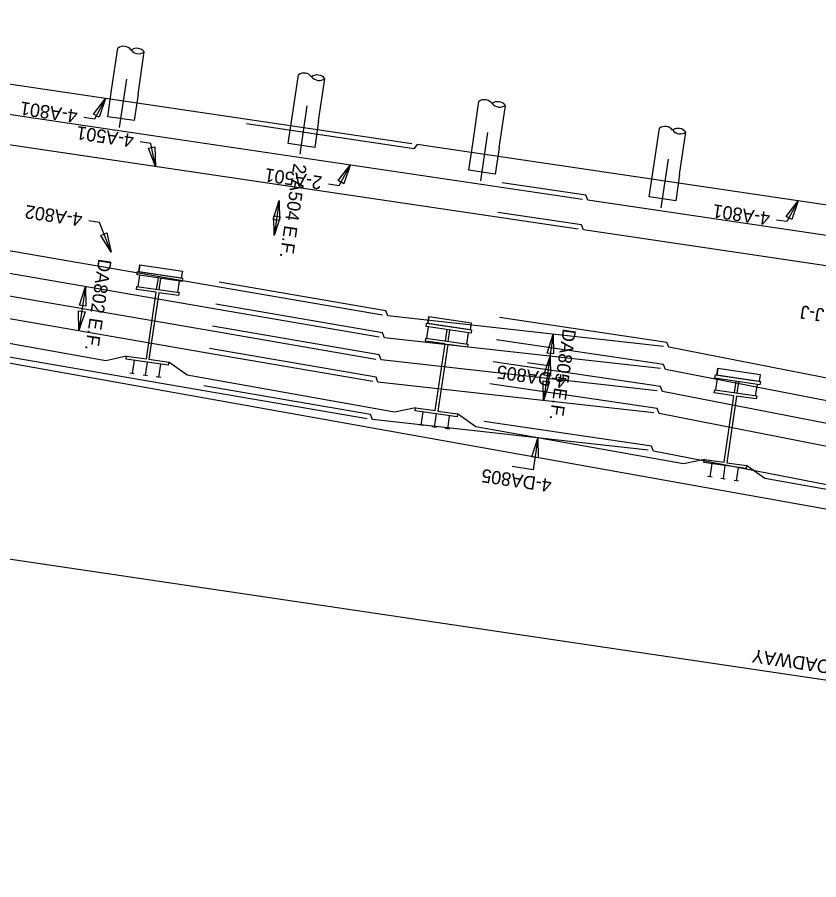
# Model space of a CAD drawing. Extents: x 1467956 to 1469946, y 573734 to 574139.
# Drawn here: x 1468989.52 to 1469019.53, y 574056.5 to 574088.79 of the extents above; entities that cross this region are included whole.
import ezdxf

# ---------------------------------------------------------------- set-up
doc = ezdxf.new("R2010")
doc.units = 0
for name, color, linetype in [('BR_P_Beam_Object', 7, 'Continuous'), ('BR_P_Beam_Stl_Det_Hidden', 7, 'Continuous'), ('BR_P_Brg_Pad_Object', 7, 'Continuous'), ('BR_P_Dia_Reinforcing', 7, 'Continuous'), ('BR_P_Gen_Text', 7, 'Continuous'), ('BR_P_Slab_Object', 7, 'Continuous'), ('BR_P_Sub_Deep_Centerline', 7, 'Continuous'), ('BR_P_Sub_Deep_Hidden', 7, 'Continuous'), ('BR_P_Sub_Deep_Object', 7, 'Continuous'), ('BR_P_Sub_Foot_Reinforcing', 7, 'Continuous'), ('Default', 7, 'Continuous')]:
    doc.layers.add(name, color=color, linetype=linetype)

# ---------------------------------------------------------------- blocks, each defined once
blk = doc.blocks.new('arrowOhio')
at = {"layer": 'Default'}
blk.add_lwpolyline([(0.00381, 0.000635), (0.00381, -0.000635), (0, 0)], close=True, dxfattribs=at)

msp = doc.modelspace()

# ---------------------------------------------------------------- linework, layer by layer
at = {"layer": 'BR_P_Beam_Object'}
for p, q in [((1468993.981, 574078.599), (1468993.998, 574078.712)), ((1468994.719, 574078.49), (1468993.981, 574078.599)), ((1468993.998, 574078.712), (1468995.573, 574078.479)), ((1468994.35, 574075.996), (1468994.719, 574078.49)), ((1468994.819, 574078.475), (1468994.449, 574075.981)), ((1468995.557, 574078.366), (1468994.819, 574078.475)), ((1468995.573, 574078.479), (1468995.557, 574078.366)), ((1469004.798, 574076.664), (1469004.815, 574076.777)), ((1469005.536, 574076.555), (1469004.798, 574076.664)), ((1469004.815, 574076.777), (1469006.39, 574076.544)), ((1469005.167, 574074.061), (1469005.536, 574076.555)), ((1469005.636, 574076.54), (1469005.266, 574074.046)), ((1469006.374, 574076.431), (1469005.636, 574076.54)), ((1469006.39, 574076.544), (1469006.374, 574076.431)), ((1468993.595, 574075.992), (1468993.612, 574076.105)), ((1468995.171, 574075.759), (1468993.595, 574075.992)), ((1468993.612, 574076.105), (1468994.35, 574075.996)), ((1468993.888, 574075.948), (1468993.815, 574075.454)), ((1468994.449, 574075.981), (1468995.187, 574075.872)), ((1468994.383, 574075.875), (1468994.31, 574075.381)), ((1468994.878, 574075.802), (1468994.804, 574075.307)), ((1468995.187, 574075.872), (1468995.171, 574075.759)), ((1468993.898, 574075.442), (1468993.733, 574075.466)), ((1468994.392, 574075.368), (1468994.227, 574075.393)), ((1468994.887, 574075.295), (1468994.722, 574075.32)), ((1469015.615, 574074.729), (1469015.632, 574074.842)), ((1469016.353, 574074.62), (1469015.615, 574074.729)), ((1469015.632, 574074.842), (1469017.207, 574074.609)), ((1469015.984, 574072.126), (1469016.353, 574074.62)), ((1469016.453, 574074.605), (1469016.083, 574072.111)), ((1469017.191, 574074.496), (1469016.453, 574074.605)), ((1469017.207, 574074.609), (1469017.191, 574074.496)), ((1469004.412, 574074.057), (1469004.429, 574074.17)), ((1469005.988, 574073.824), (1469004.412, 574074.057)), ((1469004.429, 574074.17), (1469005.167, 574074.061)), ((1469004.705, 574074.013), (1469004.632, 574073.519)), ((1469005.266, 574074.046), (1469006.004, 574073.937)), ((1469005.2, 574073.94), (1469005.127, 574073.446)), ((1469005.695, 574073.867), (1469005.621, 574073.372)), ((1469006.004, 574073.937), (1469005.988, 574073.824)), ((1469004.715, 574073.507), (1469004.55, 574073.531)), ((1469005.209, 574073.433), (1469005.044, 574073.458)), ((1469005.704, 574073.36), (1469005.539, 574073.385)), ((1469015.229, 574072.122), (1469015.246, 574072.235)), ((1469016.805, 574071.889), (1469015.229, 574072.122)), ((1469015.246, 574072.235), (1469015.984, 574072.126)), ((1469015.522, 574072.078), (1469015.449, 574071.584)), ((1469016.083, 574072.111), (1469016.821, 574072.002)), ((1469016.017, 574072.005), (1469015.944, 574071.511)), ((1469016.512, 574071.932), (1469016.438, 574071.437)), ((1469016.821, 574072.002), (1469016.805, 574071.889)), ((1469015.532, 574071.572), (1469015.367, 574071.596)), ((1469016.026, 574071.498), (1469015.861, 574071.523)), ((1469016.521, 574071.425), (1469016.356, 574071.45))]:
    msp.add_line(p, q, dxfattribs=at)
at = {"layer": 'BR_P_Beam_Stl_Det_Hidden'}
for p, q in [((1468994.039, 574078.706), (1468994.102, 574079.129)), ((1468994.736, 574078.603), (1468994.799, 574079.025)), ((1468994.835, 574078.588), (1468994.898, 574079.011)), ((1468995.532, 574078.485), (1468995.595, 574078.908)), ((1469004.856, 574076.771), (1469004.919, 574077.194)), ((1469005.553, 574076.668), (1469005.616, 574077.09)), ((1469005.652, 574076.653), (1469005.715, 574077.076)), ((1469006.349, 574076.55), (1469006.412, 574076.973)), ((1469015.673, 574074.836), (1469015.736, 574075.259)), ((1469016.37, 574074.733), (1469016.433, 574075.155)), ((1469016.469, 574074.718), (1469016.532, 574075.141)), ((1469017.166, 574074.615), (1469017.229, 574075.038))]:
    msp.add_line(p, q, dxfattribs=at)
at = {"layer": 'BR_P_Brg_Pad_Object'}
for p, q in [((1468994.111, 574079.517), (1468994.073, 574079.259)), ((1468994.005, 574079.143), (1468994.023, 574079.267)), ((1468994.023, 574079.267), (1468995.71, 574079.017)), ((1468995.699, 574079.282), (1468995.66, 574079.024)), ((1468995.692, 574078.893), (1468994.005, 574079.143)), ((1468995.71, 574079.017), (1468995.692, 574078.893)), ((1469004.928, 574077.582), (1469004.89, 574077.324)), ((1469004.822, 574077.208), (1469004.84, 574077.332)), ((1469004.84, 574077.332), (1469006.527, 574077.082)), ((1469006.516, 574077.347), (1469006.477, 574077.089)), ((1469006.509, 574076.958), (1469004.822, 574077.208)), ((1469006.527, 574077.082), (1469006.509, 574076.958)), ((1469015.745, 574075.647), (1469015.707, 574075.389)), ((1469015.639, 574075.273), (1469015.657, 574075.397)), ((1469015.657, 574075.397), (1469017.344, 574075.147)), ((1469017.333, 574075.412), (1469017.294, 574075.154)), ((1469017.326, 574075.023), (1469015.639, 574075.273)), ((1469017.344, 574075.147), (1469017.326, 574075.023))]:
    msp.add_line(p, q, dxfattribs=at)
for points in [[(1468995.699, 574079.282), (1468995.66, 574079.024), (1468994.073, 574079.259), (1468994.111, 574079.517)], [(1469006.516, 574077.347), (1469006.477, 574077.089), (1469004.89, 574077.324), (1469004.928, 574077.582)], [(1469017.333, 574075.412), (1469017.294, 574075.154), (1469015.707, 574075.389), (1469015.745, 574075.647)]]:
    msp.add_lwpolyline(points, close=True, dxfattribs=at)
at = {"layer": 'BR_P_Dia_Reinforcing'}
for p, q in [((1468980.635, 574081.53), (1468997.15, 574078.687)), ((1468980.512, 574080.703), (1468997.027, 574077.86)), ((1468980.39, 574079.875), (1468996.905, 574077.032)), ((1468980.267, 574079.048), (1468996.782, 574076.205)), ((1469003.318, 574077.799), (1468997.076, 574078.873)), ((1468997.15, 574078.687), (1469003.194, 574077.647)), ((1469003.195, 574076.971), (1468996.954, 574078.046)), ((1468997.027, 574077.86), (1469003.072, 574076.819)), ((1468980.059, 574077.644), (1468996.575, 574074.801)), ((1469003.391, 574077.613), (1469003.318, 574077.799)), ((1469013.719, 574076.46), (1469003.391, 574077.613)), ((1469013.844, 574076.617), (1469007.579, 574077.544)), ((1469003.073, 574076.144), (1468996.831, 574077.218)), ((1468996.905, 574077.032), (1469002.949, 574075.992)), ((1469003.269, 574076.785), (1469003.195, 574076.971)), ((1469013.597, 574075.633), (1469003.269, 574076.785)), ((1469013.721, 574075.789), (1469007.456, 574076.717)), ((1469013.917, 574076.431), (1469013.844, 574076.617)), ((1469002.95, 574075.316), (1468996.709, 574076.391)), ((1469035.5, 574072.215), (1469013.917, 574076.431)), ((1468996.782, 574076.205), (1469002.827, 574075.164)), ((1469003.146, 574075.958), (1469003.073, 574076.144)), ((1469013.474, 574074.805), (1469003.146, 574075.958)), ((1469013.599, 574074.962), (1469007.334, 574075.889)), ((1469013.795, 574075.603), (1469013.721, 574075.789)), ((1469035.378, 574071.387), (1469013.795, 574075.603)), ((1469003.024, 574075.13), (1469002.95, 574075.316)), ((1469002.743, 574073.913), (1468996.501, 574074.987)), ((1469013.352, 574073.978), (1469003.024, 574075.13)), ((1469013.476, 574074.134), (1469007.211, 574075.062)), ((1469013.672, 574074.776), (1469013.599, 574074.962)), ((1468996.575, 574074.801), (1469002.619, 574073.761)), ((1469035.255, 574070.56), (1469013.672, 574074.776)), ((1469013.55, 574073.948), (1469013.476, 574074.134)), ((1469002.816, 574073.727), (1469002.743, 574073.913)), ((1469013.144, 574072.574), (1469002.816, 574073.727)), ((1469035.133, 574069.732), (1469013.55, 574073.948)), ((1469013.268, 574072.731), (1469007.003, 574073.658)), ((1469013.342, 574072.545), (1469013.268, 574072.731)), ((1469034.925, 574068.328), (1469013.342, 574072.545))]:
    msp.add_line(p, q, dxfattribs=at)
at = {"layer": 'BR_P_Gen_Text'}
for p, q in [((1468992.826, 574085.749), (1468992.407, 574084.975)), ((1468992.407, 574084.975), (1468992.011, 574085.034)), ((1468994.515, 574084.06), (1468994.12, 574084.119)), ((1468994.692, 574083.198), (1468994.515, 574084.06)), ((1469001.981, 574083.256), (1469001.562, 574082.482)), ((1469001.562, 574082.482), (1469001.166, 574082.541)), ((1468999.326, 574081.922), (1468999.132, 574080.613)), ((1469018.758, 574081.91), (1469018.339, 574081.136)), ((1468992.59, 574081.104), (1468992.194, 574081.163)), ((1468993.031, 574079.988), (1468992.59, 574081.104)), ((1469018.339, 574081.136), (1469017.943, 574081.194)), ((1468992.073, 574078.713), (1468991.828, 574077.058)), ((1469009.588, 574076.921), (1469009.413, 574075.734)), ((1469009.466, 574076.094), (1469009.221, 574074.439)), ((1469009.413, 574075.734), (1469008.621, 574075.851)), ((1469009.013, 574073.035), (1469008.837, 574071.848)), ((1469008.837, 574071.848), (1469008.046, 574071.965)), ((1469070.259, 574056.497), (1468978.025, 574070.152))]:
    msp.add_line(p, q, dxfattribs=at)
at = {"layer": 'BR_P_Slab_Object'}
msp.add_line((1469026.696, 574069.14), (1468981.648, 574077.187), dxfattribs=at)
for points in [[(1468993.612, 574076.105), (1468992.828, 574075.93), (1468985.216, 574077.29), (1468984.531, 574077.783)], [(1469004.429, 574074.17), (1469003.646, 574073.998), (1468995.874, 574075.386), (1468995.187, 574075.872)], [(1469015.246, 574072.235), (1469014.463, 574072.066), (1469006.691, 574073.454), (1469006.004, 574073.937)], [(1469026.065, 574070.31), (1469025.28, 574070.134), (1469017.509, 574071.522), (1469016.821, 574072.002)]]:
    msp.add_lwpolyline(points, dxfattribs=at)
at = {"layer": 'BR_P_Sub_Deep_Centerline'}
for p, q in [((1468993.35, 574084.66), (1468993.618, 574086.474)), ((1469000.11, 574083.66), (1469000.378, 574085.473)), ((1469006.869, 574082.659), (1469007.138, 574084.473)), ((1469013.629, 574081.658), (1469013.897, 574083.472))]:
    msp.add_line(p, q, dxfattribs=at)
at = {"layer": 'BR_P_Sub_Deep_Hidden'}
for p, q in [((1468992.904, 574085.063), (1468993.051, 574086.053)), ((1468994.04, 574085.906), (1468993.893, 574084.917)), ((1468993.893, 574084.917), (1468992.904, 574085.063)), ((1468999.664, 574084.063), (1468999.81, 574085.052)), ((1469000.799, 574084.905), (1469000.653, 574083.916)), ((1469000.653, 574083.916), (1468999.664, 574084.063)), ((1469006.423, 574083.062), (1469006.57, 574084.051)), ((1469007.559, 574083.905), (1469007.413, 574082.915)), ((1469007.413, 574082.915), (1469006.423, 574083.062)), ((1469013.183, 574082.061), (1469013.329, 574083.05)), ((1469014.319, 574082.904), (1469014.172, 574081.915)), ((1469014.172, 574081.915), (1469013.183, 574082.061))]:
    msp.add_line(p, q, dxfattribs=at)
at = {"layer": 'BR_P_Sub_Deep_Object'}
for p, q in [((1468993.051, 574086.053), (1468993.285, 574087.635)), ((1468994.04, 574085.906), (1468994.274, 574087.489)), ((1468999.81, 574085.052), (1469000.044, 574086.635)), ((1469000.799, 574084.905), (1469001.034, 574086.488)), ((1469006.57, 574084.051), (1469006.804, 574085.634)), ((1469007.559, 574083.905), (1469007.793, 574085.487)), ((1469013.329, 574083.05), (1469013.564, 574084.633)), ((1469014.319, 574082.904), (1469014.553, 574084.487))]:
    msp.add_line(p, q, dxfattribs=at)
for centre, start, end in [((1468993.494, 574087.339), 37.976, 125.1816), ((1468993.988, 574087.266), 37.976, 125.1816), ((1468994.065, 574087.785), 217.976, 305.1816), ((1469000.253, 574086.338), 37.976, 125.1816), ((1469000.748, 574086.265), 37.976, 125.1816), ((1469000.825, 574086.784), 217.976, 305.1816), ((1469007.013, 574085.338), 37.976, 125.1816), ((1469007.508, 574085.264), 37.976, 125.1816), ((1469007.584, 574085.784), 217.976, 305.1816), ((1469013.773, 574084.337), 37.976, 125.1816), ((1469014.267, 574084.264), 37.976, 125.1816), ((1469014.344, 574084.783), 217.976, 305.1816)]:
    msp.add_arc(centre, 0.362, start, end, dxfattribs=at)
at = {"layer": 'BR_P_Sub_Foot_Reinforcing'}
for p, q in [((1469004.297, 574084.051), (1468972.298, 574088.788)), ((1469010.688, 574081.967), (1468972.133, 574087.675)), ((1469010.523, 574080.854), (1468971.968, 574086.562))]:
    msp.add_line(p, q, dxfattribs=at)
for points in [[(1469030.229, 574080.212), (1469004.495, 574084.021), (1469004.371, 574083.865), (1468998.106, 574084.792)], [(1469046.308, 574076.694), (1469010.886, 574081.938), (1469010.812, 574082.124), (1469007.68, 574082.588)], [(1469046.144, 574075.581), (1469010.721, 574080.825), (1469010.648, 574081.011), (1469007.515, 574081.475)]]:
    msp.add_lwpolyline(points, dxfattribs=at)

# ---------------------------------------------------------------- block references
at = {"layer": 'BR_P_Gen_Text'}
for p, xscale, yscale, rotation in [((1468992.826, 574085.749), 191.49567999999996, 191.49568, -118.42123067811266), ((1468994.692, 574083.198), 191.49567999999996, 191.49568, 101.57876932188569), ((1469001.981, 574083.256), 191.49567999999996, 191.49568, -118.42123067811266), ((1468999.326, 574081.922), 191.49568000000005, 191.49568, -98.42123067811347), ((1469018.758, 574081.91), 191.49567999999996, 191.49568, -118.42123067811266), ((1468999.132, 574080.613), 191.49568000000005, 191.49568, 81.57876932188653), ((1468993.031, 574079.988), 191.49568000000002, 191.49568000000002, 111.57876932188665), ((1468992.073, 574078.713), 191.49568000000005, 191.49568, -98.42123067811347), ((1468991.828, 574077.058), 191.49568000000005, 191.49568, 81.57876932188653), ((1469009.588, 574076.921), 191.49568000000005, 191.49568, -98.42123067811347), ((1469009.466, 574076.094), 191.49568000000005, 191.49568, -98.42123067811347), ((1469009.221, 574074.439), 191.49568000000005, 191.49568, 81.57876932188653), ((1469009.013, 574073.035), 191.49568000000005, 191.49568, -98.42123067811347)]:
    msp.add_blockref('arrowOhio', p, dxfattribs=dict(at, xscale=xscale, yscale=yscale, rotation=rotation))

# ---------------------------------------------------------------- texts
for s, rotation, p in [('4-A801', 171.5788, (1468991.8, 574085.318)), ('4-A501', 171.5788, (1468993.909, 574084.403)), ('2-A501', 171.5788, (1469000.956, 574082.825)), ('2-A504 E.F.', 261.5788, (1468999.864, 574083.332)), ('4-A802', 171.5788, (1468991.983, 574081.447)), ('4-A801', 171.5788, (1469017.732, 574081.478)), ('DA802 E.F.', 261.5788, (1468992.558, 574079.763)), ('SEE VIEW J-J', 171.5788, (1469023.137, 574077.377)), ('DA805 E.F.', 261.5788, (1469009.951, 574077.148)), ('4-DA805', 171.5788, (1469010.126, 574075.38)), ('4-DA805', 171.5788, (1469009.55, 574071.494)), ('MEASURED PERPENDICULAR TO C ROADWAY', 171.5788, (1469031.992, 574062.924))]:
    msp.add_text(s, height=0.5, rotation=rotation, dxfattribs=at).set_placement(p)

doc.saveas('drawing.dxf')
